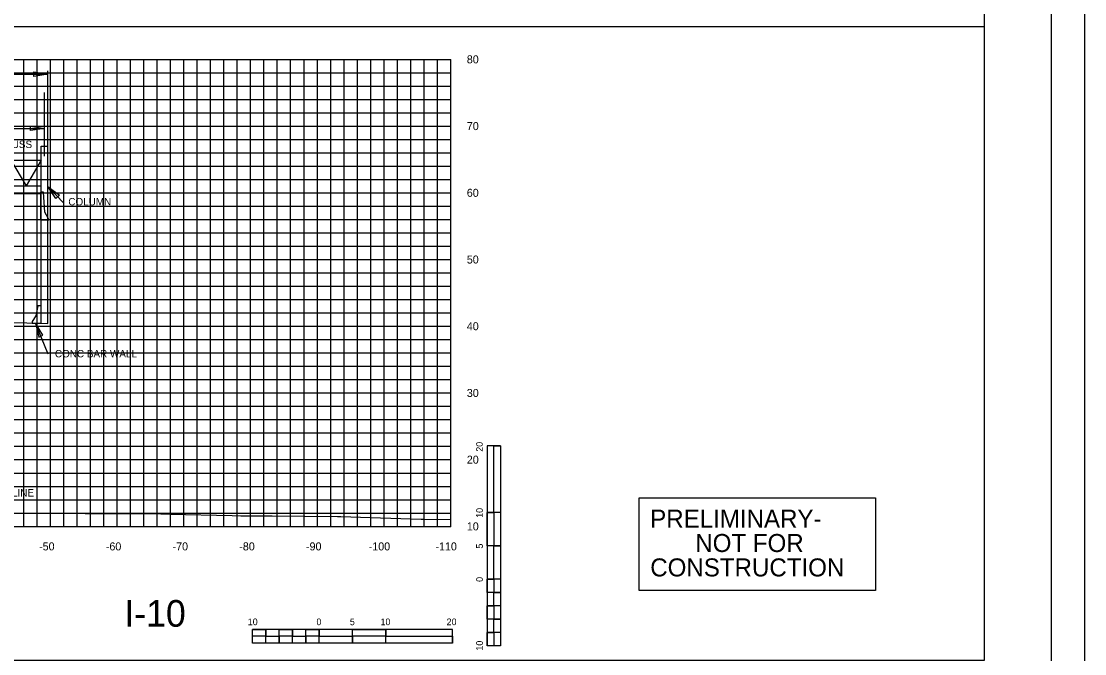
# Model space of a CAD drawing. Extents: x 2193008 to 2198143, y 1236112 to 1237864.
# Drawn here: x 2195038.5 to 2195197.9, y 1237134 to 1237228.8 of the extents above; entities that cross this region are included whole.
import ezdxf

# ---------------------------------------------------------------- set-up
doc = ezdxf.new("R2010")
doc.units = 0
for name, color, linetype in [('1', 7, 'Continuous'), ('10', 7, 'Continuous'), ('3', 7, 'Continuous'), ('31', 7, 'Continuous'), ('60', 7, 'Continuous'), ('CL-CNST', 7, 'Continuous'), ('GSBWFILL', 7, 'Continuous'), ('GSDIMS', 7, 'Continuous'), ('Level 1', 7, 'Continuous'), ('Level 33', 7, 'Continuous'), ('Level 55', 7, 'Continuous'), ('Level 62', 7, 'Continuous'), ('M-ROADS', 7, 'Continuous'), ('SHT-BDR', 7, 'Continuous'), ('SHT-BNDRY', 7, 'Continuous')]:
    doc.layers.add(name, color=color, linetype=linetype)

msp = doc.modelspace()

# ---------------------------------------------------------------- linework, layer by layer
msp.add_line((2195041.99, 1237208.58), (2195041.99, 1237218.12))
msp.add_lwpolyline([(2195041.49, 1237183.55), (2195041.48, 1237186.19), (2195040.98, 1237186.19), (2195040.69, 1237184.67), (2195040.11, 1237183.83), (2195040.11, 1237183.58)], close=True)
at = {"layer": '1'}
msp.add_lwpolyline([(2195131.07, 1237157.4), (2195166.53, 1237157.4), (2195166.53, 1237143.51), (2195131.07, 1237143.51)], close=True, dxfattribs=at)
at = {"layer": '3'}
for p, q in [((2194882.86, 1237228.05), (2195182.86, 1237228.05)), ((2195042.49, 1237210.11), (2195042.49, 1237221.37)), ((2194992.36, 1237220.88), (2195042.49, 1237220.88)), ((2195041.49, 1237183.55), (2195041.49, 1237210.11)), ((2195042.49, 1237183.53), (2195042.49, 1237210.11)), ((2195044.85, 1237201.58), (2195042.49, 1237204.03)), ((2195042.52, 1237178.94), (2195040.62, 1237183.56))]:
    msp.add_line(p, q, dxfattribs=at)
at = {"layer": '60'}
for p, q in [((2195102.86, 1237153.11), (2195102.86, 1237223.11)), ((2195102.92, 1237213.11), (2195102.86, 1237213.11)), ((2195102.92, 1237203.11), (2195102.86, 1237203.11)), ((2195102.92, 1237193.11), (2195102.86, 1237193.11)), ((2195102.92, 1237183.11), (2195102.86, 1237183.11)), ((2195102.92, 1237173.11), (2195102.86, 1237173.11)), ((2195102.92, 1237163.11), (2195102.86, 1237163.11)), ((2194972.86, 1237153.11), (2195102.86, 1237153.11)), ((2195042.86, 1237153.05), (2195042.86, 1237153.11)), ((2195052.86, 1237153.05), (2195052.86, 1237153.11)), ((2195062.86, 1237153.05), (2195062.86, 1237153.11)), ((2195072.86, 1237153.05), (2195072.86, 1237153.11)), ((2195082.86, 1237153.05), (2195082.86, 1237153.11)), ((2195092.86, 1237153.05), (2195092.86, 1237153.11)), ((2195102.86, 1237153.05), (2195102.86, 1237153.11)), ((2195102.92, 1237153.11), (2195102.86, 1237153.11))]:
    msp.add_line(p, q, dxfattribs=at)
at = {"layer": 'CL-CNST'}
msp.add_lwpolyline([(2194972.86, 1237184.04), (2194980.84, 1237183.86), (2194981.61, 1237183.85), (2194990.97, 1237183.64), (2194991.61, 1237183.63), (2194992.78, 1237183.6), (2194992.86, 1237183.6), (2194992.86, 1237183.6), (2194992.86, 1237183.6), (2194994.03, 1237183.62), (2194994.11, 1237183.63), (2195003.47, 1237183.83), (2195004.11, 1237183.85), (2195015.34, 1237184.09), (2195016.11, 1237184.11), (2195027.34, 1237183.86), (2195028.11, 1237183.85), (2195039.34, 1237183.6), (2195042.49, 1237183.53)], dxfattribs=at)
at = {"layer": 'GSBWFILL'}
msp.add_lwpolyline([(2195041.84, 1237203.23), (2195041.36, 1237203.23), (2195041.36, 1237199.05), (2195042.59, 1237199.05), (2195042.61, 1237199.05), (2195042.59, 1237199.22), (2195042.04, 1237200.22), (2195041.84, 1237203.23)], dxfattribs=at)
at = {"layer": 'GSDIMS'}
for p, q in [((2195030.65, 1237212.77), (2195041.99, 1237212.77)), ((2195030.65, 1237209.11), (2195041.49, 1237209.11)), ((2195041.49, 1237210.11), (2195042.49, 1237210.11)), ((2195030.65, 1237208), (2195041.49, 1237208)), ((2195036.93, 1237208), (2195039.21, 1237204.14)), ((2195041.49, 1237208), (2195039.21, 1237204.14)), ((2195030.65, 1237204.14), (2195041.49, 1237204.14)), ((2195030.65, 1237203.03), (2195041.49, 1237203.03))]:
    msp.add_line(p, q, dxfattribs=at)
for points in [[(2195042.49, 1237220.88), (2195040.36, 1237220.54), (2195040.36, 1237221.23)], [(2195041.99, 1237212.77), (2195039.86, 1237212.43), (2195039.86, 1237213.12)], [(2195042.49, 1237204.03), (2195044.21, 1237202.75), (2195043.69, 1237202.28)], [(2195040.62, 1237183.56), (2195041.1, 1237181.48), (2195041.74, 1237181.76)]]:
    msp.add_lwpolyline(points, close=True, dxfattribs=at)
at = {"layer": 'Level 1'}
for p, q in [((2195108.33, 1237165.19), (2195108.33, 1237135.19)), ((2195110.33, 1237165.19), (2195108.33, 1237165.19)), ((2195110.33, 1237165.19), (2195110.33, 1237155.19)), ((2195110.33, 1237165.19), (2195110.33, 1237135.19)), ((2195109.33, 1237155.19), (2195108.33, 1237155.19)), ((2195110.33, 1237155.19), (2195108.33, 1237155.19)), ((2195109.33, 1237155.19), (2195109.33, 1237150.19)), ((2195110.33, 1237150.19), (2195108.33, 1237150.19)), ((2195110.33, 1237150.19), (2195109.33, 1237150.19)), ((2195110.33, 1237150.19), (2195110.33, 1237145.19)), ((2195109.33, 1237145.19), (2195108.33, 1237145.19)), ((2195110.33, 1237145.19), (2195108.33, 1237145.19)), ((2195109.33, 1237145.19), (2195109.33, 1237143.19)), ((2195110.33, 1237143.19), (2195109.33, 1237143.19)), ((2195110.33, 1237143.19), (2195110.33, 1237141.19)), ((2195109.33, 1237141.19), (2195108.33, 1237141.19)), ((2195109.33, 1237141.19), (2195109.33, 1237139.19)), ((2195110.33, 1237139.19), (2195109.33, 1237139.19)), ((2195110.33, 1237139.19), (2195110.33, 1237137.19)), ((2195103.13, 1237137.63), (2195073.13, 1237137.63)), ((2195073.13, 1237135.63), (2195073.13, 1237137.63)), ((2195075.13, 1237136.63), (2195075.13, 1237137.63)), ((2195079.13, 1237136.63), (2195079.13, 1237137.63)), ((2195083.13, 1237136.63), (2195083.13, 1237137.63)), ((2195083.13, 1237135.63), (2195083.13, 1237137.63)), ((2195088.13, 1237135.63), (2195088.13, 1237137.63)), ((2195093.13, 1237136.63), (2195093.13, 1237137.63)), ((2195093.13, 1237135.63), (2195093.13, 1237137.63)), ((2195103.13, 1237135.63), (2195103.13, 1237137.63)), ((2195109.33, 1237137.19), (2195108.33, 1237137.19)), ((2195109.33, 1237137.19), (2195109.33, 1237135.19)), ((2195075.13, 1237136.63), (2195073.13, 1237136.63)), ((2195103.13, 1237135.63), (2195073.13, 1237135.63)), ((2195077.13, 1237135.63), (2195075.13, 1237135.63)), ((2195077.13, 1237135.63), (2195077.13, 1237136.63)), ((2195079.13, 1237136.63), (2195077.13, 1237136.63)), ((2195081.13, 1237135.63), (2195079.13, 1237135.63)), ((2195081.13, 1237135.63), (2195081.13, 1237136.63)), ((2195083.13, 1237136.63), (2195081.13, 1237136.63)), ((2195088.13, 1237135.63), (2195083.13, 1237135.63)), ((2195088.13, 1237135.63), (2195088.13, 1237136.63)), ((2195093.13, 1237136.63), (2195088.13, 1237136.63)), ((2195103.13, 1237135.63), (2195093.13, 1237135.63)), ((2195110.33, 1237135.19), (2195108.33, 1237135.19))]:
    msp.add_line(p, q, dxfattribs=at)
for points in [[(2195109.33, 1237155.19), (2195109.33, 1237165.19), (2195110.33, 1237165.19), (2195110.33, 1237155.19)], [(2195108.33, 1237150.19), (2195108.33, 1237155.19), (2195109.33, 1237155.19), (2195109.33, 1237150.19)], [(2195109.33, 1237145.19), (2195109.33, 1237150.19), (2195110.33, 1237150.19), (2195110.33, 1237145.19)], [(2195108.33, 1237143.19), (2195108.33, 1237145.19), (2195109.33, 1237145.19), (2195109.33, 1237143.19)], [(2195109.33, 1237141.19), (2195109.33, 1237143.19), (2195110.33, 1237143.19), (2195110.33, 1237141.19)], [(2195108.33, 1237139.19), (2195108.33, 1237141.19), (2195109.33, 1237141.19), (2195109.33, 1237139.19)], [(2195109.33, 1237137.19), (2195109.33, 1237139.19), (2195110.33, 1237139.19), (2195110.33, 1237137.19)], [(2195073.13, 1237137.63), (2195075.13, 1237137.63), (2195075.13, 1237136.63), (2195073.13, 1237136.63)], [(2195077.13, 1237137.63), (2195079.13, 1237137.63), (2195079.13, 1237136.63), (2195077.13, 1237136.63)], [(2195081.13, 1237137.63), (2195083.13, 1237137.63), (2195083.13, 1237136.63), (2195081.13, 1237136.63)], [(2195088.13, 1237137.63), (2195093.13, 1237137.63), (2195093.13, 1237136.63), (2195088.13, 1237136.63)], [(2195108.33, 1237135.19), (2195108.33, 1237137.19), (2195109.33, 1237137.19), (2195109.33, 1237135.19)], [(2195075.13, 1237136.63), (2195077.13, 1237136.63), (2195077.13, 1237135.63), (2195075.13, 1237135.63)], [(2195079.13, 1237136.63), (2195081.13, 1237136.63), (2195081.13, 1237135.63), (2195079.13, 1237135.63)], [(2195083.13, 1237136.63), (2195088.13, 1237136.63), (2195088.13, 1237135.63), (2195083.13, 1237135.63)], [(2195093.13, 1237136.63), (2195103.13, 1237136.63), (2195103.13, 1237135.63), (2195093.13, 1237135.63)]]:
    msp.add_lwpolyline(points, close=True, dxfattribs=at)
at = {"layer": 'Level 62'}
for p, q in [((2194972.86, 1237223.11), (2195102.86, 1237223.11)), ((2195038.86, 1237153.11), (2195038.86, 1237223.11)), ((2195040.86, 1237153.11), (2195040.86, 1237223.11)), ((2195042.86, 1237153.11), (2195042.86, 1237223.11)), ((2195044.86, 1237153.11), (2195044.86, 1237223.11)), ((2195046.86, 1237153.11), (2195046.86, 1237223.11)), ((2195048.86, 1237153.11), (2195048.86, 1237223.11)), ((2195050.86, 1237153.11), (2195050.86, 1237223.11)), ((2195052.86, 1237153.11), (2195052.86, 1237223.11)), ((2195054.86, 1237153.11), (2195054.86, 1237223.11)), ((2195056.86, 1237153.11), (2195056.86, 1237223.11)), ((2195058.86, 1237153.11), (2195058.86, 1237223.11)), ((2195060.86, 1237153.11), (2195060.86, 1237223.11)), ((2195062.86, 1237153.11), (2195062.86, 1237223.11)), ((2195064.86, 1237153.11), (2195064.86, 1237223.11)), ((2195066.86, 1237153.11), (2195066.86, 1237223.11)), ((2195068.86, 1237153.11), (2195068.86, 1237223.11)), ((2195070.86, 1237153.11), (2195070.86, 1237223.11)), ((2195072.86, 1237153.11), (2195072.86, 1237223.11)), ((2195074.86, 1237153.11), (2195074.86, 1237223.11)), ((2195076.86, 1237153.11), (2195076.86, 1237223.11)), ((2195078.86, 1237153.11), (2195078.86, 1237223.11)), ((2195080.86, 1237153.11), (2195080.86, 1237223.11)), ((2195082.86, 1237153.11), (2195082.86, 1237223.11)), ((2195084.86, 1237153.11), (2195084.86, 1237223.11)), ((2195086.86, 1237153.11), (2195086.86, 1237223.11)), ((2195088.86, 1237153.11), (2195088.86, 1237223.11)), ((2195090.86, 1237153.11), (2195090.86, 1237223.11)), ((2195092.86, 1237153.11), (2195092.86, 1237223.11)), ((2195094.86, 1237153.11), (2195094.86, 1237223.11)), ((2195096.86, 1237153.11), (2195096.86, 1237223.11)), ((2195098.86, 1237153.11), (2195098.86, 1237223.11)), ((2195100.86, 1237153.11), (2195100.86, 1237223.11)), ((2195102.86, 1237153.11), (2195102.86, 1237223.11)), ((2194972.86, 1237221.11), (2195102.86, 1237221.11)), ((2194972.86, 1237219.11), (2195102.86, 1237219.11)), ((2194972.86, 1237217.11), (2195102.86, 1237217.11)), ((2194972.86, 1237215.11), (2195102.86, 1237215.11)), ((2194972.86, 1237213.11), (2195102.86, 1237213.11)), ((2194972.86, 1237211.11), (2195102.86, 1237211.11)), ((2194972.86, 1237209.11), (2195102.86, 1237209.11)), ((2194972.86, 1237207.11), (2195102.86, 1237207.11)), ((2194972.86, 1237205.11), (2195102.86, 1237205.11)), ((2194972.86, 1237203.11), (2195102.86, 1237203.11)), ((2194972.86, 1237201.11), (2195102.86, 1237201.11)), ((2194972.86, 1237199.11), (2195102.86, 1237199.11)), ((2194972.86, 1237197.11), (2195102.86, 1237197.11)), ((2194972.86, 1237195.11), (2195102.86, 1237195.11)), ((2194972.86, 1237193.11), (2195102.86, 1237193.11)), ((2194972.86, 1237191.11), (2195102.86, 1237191.11)), ((2194972.86, 1237189.11), (2195102.86, 1237189.11)), ((2194972.86, 1237187.11), (2195102.86, 1237187.11)), ((2194972.86, 1237185.11), (2195102.86, 1237185.11)), ((2194972.86, 1237183.11), (2195102.86, 1237183.11)), ((2194972.86, 1237181.11), (2195102.86, 1237181.11)), ((2194972.86, 1237179.11), (2195102.86, 1237179.11)), ((2194972.86, 1237177.11), (2195102.86, 1237177.11)), ((2194972.86, 1237175.11), (2195102.86, 1237175.11)), ((2194972.86, 1237173.11), (2195102.86, 1237173.11)), ((2194972.86, 1237171.11), (2195102.86, 1237171.11)), ((2194972.86, 1237169.11), (2195102.86, 1237169.11)), ((2194972.86, 1237167.11), (2195102.86, 1237167.11)), ((2194972.86, 1237165.11), (2195102.86, 1237165.11)), ((2194972.86, 1237163.11), (2195102.86, 1237163.11)), ((2194972.86, 1237161.11), (2195102.86, 1237161.11)), ((2194972.86, 1237159.11), (2195102.86, 1237159.11)), ((2194972.86, 1237157.11), (2195102.86, 1237157.11)), ((2194972.86, 1237155.11), (2195102.86, 1237155.11)), ((2194972.86, 1237153.11), (2195102.86, 1237153.11))]:
    msp.add_line(p, q, dxfattribs=at)
msp.add_lwpolyline([(2194857.86, 1237118.04), (2195197.86, 1237118.04), (2195197.86, 1237338.04), (2194857.86, 1237338.04)], close=True, dxfattribs=at)
at = {"layer": 'M-ROADS'}
msp.add_lwpolyline([(2194999.86, 1237155.11), (2195048.06, 1237155.06), (2195049.92, 1237155.06), (2195056.3, 1237155.05), (2195056.79, 1237155.05), (2195056.8, 1237155.05), (2195057.8, 1237155.03), (2195058.06, 1237155.03), (2195060.77, 1237154.96), (2195070.09, 1237154.75), (2195071.38, 1237154.71), (2195071.84, 1237154.71), (2195075.79, 1237154.7), (2195076.07, 1237154.7), (2195085.89, 1237154.58), (2195086.09, 1237154.58), (2195086.4, 1237154.58), (2195090.85, 1237154.43), (2195098.41, 1237154.2), (2195098.78, 1237154.2), (2195098.91, 1237154.2), (2195102.86, 1237154.13)], dxfattribs=at)
at = {"layer": 'SHT-BDR'}
msp.add_lwpolyline([(2194882.86, 1237133.05), (2195182.86, 1237133.05), (2195182.86, 1237323.05), (2194882.86, 1237323.05)], close=True, dxfattribs=at)
at = {"layer": 'SHT-BNDRY'}
msp.add_lwpolyline([(2194870.36, 1237123.04), (2195192.86, 1237123.04), (2195192.86, 1237333.04), (2194870.36, 1237333.04)], close=True, dxfattribs=at)

# ---------------------------------------------------------------- texts
at = {"layer": '1'}
for s, p in [('PRELIMINARY-', (2195132.74, 1237152.92)), ('NOT FOR', (2195139.5, 1237149.27)), ('CONSTRUCTION', (2195132.75, 1237145.61))]:
    msp.add_text(s, height=2.7, dxfattribs=at).set_placement(p)
at = {"layer": '10'}
for s, p in [('-50', (2195041.16, 1237149.51)), ('-60', (2195051.16, 1237149.51)), ('-70', (2195061.16, 1237149.51)), ('-80', (2195071.16, 1237149.51)), ('-90', (2195081.16, 1237149.51)), ('-100', (2195090.56, 1237149.51)), ('-110', (2195100.56, 1237149.51))]:
    msp.add_text(s, height=1.2, dxfattribs=at).set_placement(p)
at = {"layer": '31'}
for s, p in [('80', (2195105.26, 1237222.51)), ('70', (2195105.26, 1237212.51)), ('60', (2195105.26, 1237202.51)), ('50', (2195105.26, 1237192.51)), ('40', (2195105.26, 1237182.51)), ('30', (2195105.26, 1237172.51)), ('20', (2195105.26, 1237162.51)), ('10', (2195105.26, 1237152.51))]:
    msp.add_text(s, height=1.2, dxfattribs=at).set_placement(p)
at = {"layer": 'Level 1'}
for s, height, rotation, p in [('20', 0.999, 90.0572, (2195107.66, 1237164.3)), ('10', 0.999, 90.0572, (2195107.66, 1237154.39)), ('5', 1, 90.0572, (2195107.66, 1237149.78)), ('0', 1, 90.0572, (2195107.66, 1237144.79)), ('10', 0.999, 0.0572, (2195072.43, 1237138.3)), ('0', 1, 0.0572, (2195082.73, 1237138.3)), ('5', 0.999, 0.0572, (2195087.73, 1237138.3)), ('10', 0.999, 0.0572, (2195092.33, 1237138.3)), ('20', 0.999, 0.0572, (2195102.23, 1237138.3)), ('10', 0.999, 90.0572, (2195107.66, 1237134.49))]:
    msp.add_text(s, height=height, rotation=rotation, dxfattribs=at).set_placement(p)
at = {"layer": 'Level 33'}
msp.add_text('I-10', height=3.998, rotation=360, dxfattribs=at).set_placement((2195053.93, 1237138.07))
at = {"layer": 'Level 55'}
for s, height, p in [('SIGN TRUSS', 1.11, (2195031.04, 1237209.82)), ('COLUMN', 1.11, (2195045.54, 1237201.22)), ('CONC BAR WALL', 1.1105, (2195043.53, 1237178.44)), ('EX GROUND LINE', 1.1105, (2195027.7, 1237157.58))]:
    msp.add_text(s, height=height, dxfattribs=at).set_placement(p)

doc.saveas('drawing.dxf')
